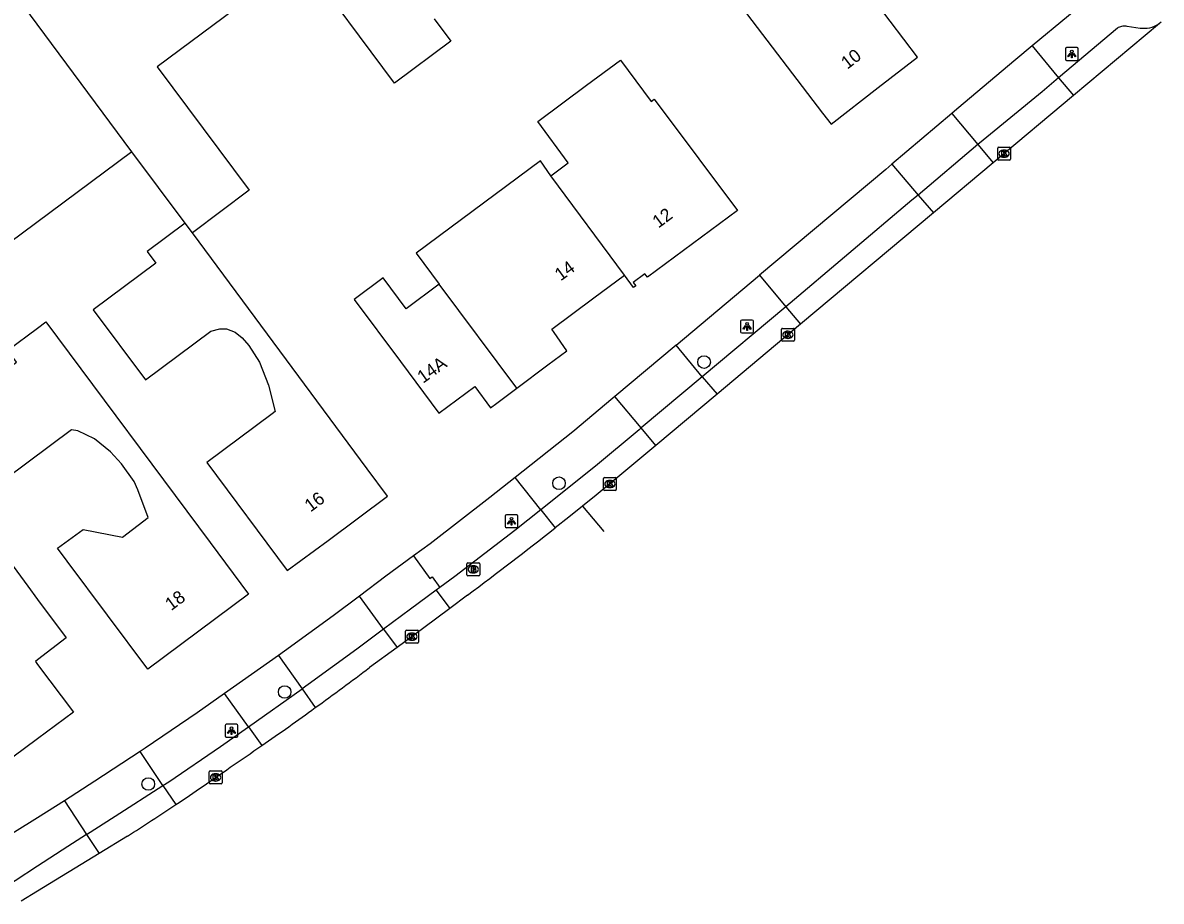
# Model space of a CAD drawing. Extents: x 156651 to 158072, y 387631 to 388990.
# Drawn here: x 157498.9 to 157587.2, y 387835.5 to 387903.7 of the extents above; entities that cross this region are included whole.
import ezdxf

# ---------------------------------------------------------------- set-up
doc = ezdxf.new("R2010")
doc.units = 0
for name, color, linetype in [('IMGEO_Boom', 7, 'Continuous'), ('IMGEO_Brandkraan', 7, 'Continuous'), ('IMGEO_Kolk', 7, 'Continuous'), ('IMGEO_Lichtpunt', 7, 'Continuous'), ('IMGEO_Pand', 7, 'Continuous'), ('IMGEO_Pand_nummerreeks', 7, 'Continuous'), ('IMGEO_Rijbaan_lokaal_open', 7, 'Continuous'), ('IMGEO_Voetpad_open', 7, 'Continuous')]:
    doc.layers.add(name, color=color, linetype=linetype)

msp = doc.modelspace()

# ---------------------------------------------------------------- linework, layer by layer
at = {"layer": 'IMGEO_Boom'}
for centre in [(157551.702, 387877.341), (157540.452, 387867.941), (157519.169, 387851.758), (157508.585, 387844.622)]:
    msp.add_circle(centre, 0.489, dxfattribs=at)
at = {"layer": 'IMGEO_Brandkraan'}
for p, q in [((157533.297, 387860.84), (157533.297, 387861.692)), ((157533.372, 387861.766), (157534.224, 387861.766)), ((157534.298, 387861.692), (157534.298, 387860.84)), ((157534.224, 387860.766), (157533.372, 387860.766)), ((157533.808, 387860.986), (157533.783, 387860.986)), ((157533.785, 387861.546), (157533.81, 387861.546))]:
    msp.add_line(p, q, dxfattribs=at)
for points in [[(157533.297, 387860.84), (157533.297, 387861.692)], [(157533.372, 387861.766), (157534.224, 387861.766)], [(157534.298, 387861.692), (157534.298, 387860.84)], [(157534.224, 387860.766), (157533.372, 387860.766)], [(157533.645, 387861.466), (157533.645, 387861.066), (157533.858, 387861.066)], [(157533.876, 387861.466), (157533.645, 387861.466)], [(157533.824, 387861.385), (157533.77, 387861.385), (157533.77, 387861.309)], [(157533.77, 387861.309), (157533.823, 387861.309)], [(157533.832, 387861.233), (157533.77, 387861.233), (157533.77, 387861.152)], [(157533.77, 387861.152), (157533.832, 387861.152)]]:
    msp.add_lwpolyline(points, dxfattribs=at)
for centre, radius, start, end in [((157533.374, 387861.69), 0.0765, 91.55205, 178.44795), ((157533.374, 387861.69), 0.0765, 91.55205, 178.44795), ((157534.222, 387861.69), 0.0765, 1.55205, 88.44795), ((157534.222, 387861.69), 0.0765, 1.55205, 88.44795), ((157533.374, 387860.842), 0.0765, 181.55205, 268.44795), ((157533.374, 387860.842), 0.0765, 181.55205, 268.44795), ((157533.825, 387861.347), 0.0379, 267.82845, 90.93552), ((157533.833, 387861.192), 0.0404, 269.87594, 90.50774), ((157533.864, 387861.317), 0.251, 268.66757, 293.53466), ((157533.88, 387861.321), 0.145, 59.4692, 91.53667), ((157533.905, 387861.368), 0.0922, 285.51372, 58.15012), ((157533.91, 387861.176), 0.105, 301.31148, 78.98903), ((157534.222, 387860.842), 0.0765, 271.55205, 358.44795), ((157534.222, 387860.842), 0.0765, 271.55205, 358.44795)]:
    msp.add_arc(centre, radius, start, end, dxfattribs=at)
for centre, major_axis, ratio, start_param, end_param in [((157533.784, 387861.266), (-0.387, 0.002), 0.722429, 4.712389, 7.853982), ((157533.809, 387861.266), (-0.39, 0.002), 0.717154, 1.570796, 4.712389)]:
    msp.add_ellipse(centre, major_axis=major_axis, ratio=ratio, start_param=start_param, end_param=end_param, dxfattribs=at)
at = {"layer": 'IMGEO_Kolk'}
for p, q in [((157574.484, 387893.08), (157574.484, 387893.932)), ((157574.559, 387894.006), (157575.411, 387894.006)), ((157574.972, 387893.786), (157574.997, 387893.786)), ((157575.485, 387893.932), (157575.485, 387893.08)), ((157575.411, 387893.006), (157574.559, 387893.006)), ((157574.995, 387893.226), (157574.97, 387893.226)), ((157557.708, 387879.03), (157557.708, 387879.882)), ((157557.783, 387879.956), (157558.635, 387879.956)), ((157558.196, 387879.736), (157558.221, 387879.736)), ((157558.709, 387879.882), (157558.709, 387879.03)), ((157558.635, 387878.956), (157557.783, 387878.956)), ((157558.219, 387879.176), (157558.194, 387879.176)), ((157543.896, 387867.463), (157543.896, 387868.315)), ((157543.971, 387868.389), (157544.823, 387868.389)), ((157544.384, 387868.169), (157544.409, 387868.169)), ((157544.897, 387868.315), (157544.897, 387867.463)), ((157544.823, 387867.389), (157543.971, 387867.389)), ((157544.407, 387867.609), (157544.382, 387867.609)), ((157528.542, 387855.624), (157528.542, 387856.476)), ((157528.617, 387856.55), (157529.469, 387856.55)), ((157529.03, 387856.33), (157529.055, 387856.33)), ((157529.543, 387856.476), (157529.543, 387855.624)), ((157529.469, 387855.55), (157528.617, 387855.55)), ((157529.053, 387855.77), (157529.028, 387855.77)), ((157513.311, 387844.706), (157513.311, 387845.558)), ((157513.386, 387845.632), (157514.238, 387845.632)), ((157513.822, 387844.852), (157513.797, 387844.852)), ((157513.799, 387845.412), (157513.824, 387845.412)), ((157514.312, 387845.558), (157514.312, 387844.706)), ((157514.238, 387844.632), (157513.386, 387844.632))]:
    msp.add_line(p, q, dxfattribs=at)
for points in [[(157574.484, 387893.08), (157574.484, 387893.932)], [(157574.559, 387894.006), (157575.411, 387894.006)], [(157574.805, 387893.706), (157574.928, 387893.706), (157574.928, 387893.555), (157575.058, 387893.706), (157575.222, 387893.706), (157575.076, 387893.555), (157575.229, 387893.306), (157575.077, 387893.306), (157574.992, 387893.47), (157574.928, 387893.403), (157574.928, 387893.306), (157574.805, 387893.306), (157574.805, 387893.706)], [(157575.485, 387893.932), (157575.485, 387893.08)], [(157575.411, 387893.006), (157574.559, 387893.006)], [(157557.708, 387879.03), (157557.708, 387879.882)], [(157557.783, 387879.956), (157558.635, 387879.956)], [(157558.029, 387879.656), (157558.152, 387879.656), (157558.152, 387879.505), (157558.282, 387879.656), (157558.446, 387879.656), (157558.3, 387879.505), (157558.453, 387879.256), (157558.301, 387879.256), (157558.216, 387879.42), (157558.152, 387879.353), (157558.152, 387879.256), (157558.029, 387879.256), (157558.029, 387879.656)], [(157558.709, 387879.882), (157558.709, 387879.03)], [(157558.635, 387878.956), (157557.783, 387878.956)], [(157543.896, 387867.463), (157543.896, 387868.315)], [(157543.971, 387868.389), (157544.823, 387868.389)], [(157544.217, 387868.089), (157544.34, 387868.089), (157544.34, 387867.938), (157544.47, 387868.089), (157544.634, 387868.089), (157544.488, 387867.938), (157544.641, 387867.689), (157544.489, 387867.689), (157544.404, 387867.853), (157544.34, 387867.786), (157544.34, 387867.689), (157544.217, 387867.689), (157544.217, 387868.089)], [(157544.897, 387868.315), (157544.897, 387867.463)], [(157544.823, 387867.389), (157543.971, 387867.389)], [(157528.542, 387855.624), (157528.542, 387856.476)], [(157528.617, 387856.55), (157529.469, 387856.55)], [(157529.543, 387856.476), (157529.543, 387855.624)], [(157529.469, 387855.55), (157528.617, 387855.55)], [(157528.863, 387856.25), (157528.986, 387856.25), (157528.986, 387856.099), (157529.116, 387856.25), (157529.28, 387856.25), (157529.134, 387856.099), (157529.287, 387855.85), (157529.135, 387855.85), (157529.05, 387856.014), (157528.986, 387855.947), (157528.986, 387855.85), (157528.863, 387855.85), (157528.863, 387856.25)], [(157513.311, 387844.706), (157513.311, 387845.558)], [(157513.386, 387845.632), (157514.238, 387845.632)], [(157513.632, 387845.332), (157513.755, 387845.332), (157513.755, 387845.181), (157513.885, 387845.332), (157514.049, 387845.332), (157513.903, 387845.181), (157514.056, 387844.932), (157513.904, 387844.932), (157513.819, 387845.096), (157513.755, 387845.029), (157513.755, 387844.932), (157513.632, 387844.932), (157513.632, 387845.332)], [(157514.312, 387845.558), (157514.312, 387844.706)], [(157514.238, 387844.632), (157513.386, 387844.632)]]:
    msp.add_lwpolyline(points, dxfattribs=at)
for centre, start, end in [((157574.561, 387893.93), 91.55205, 178.44795), ((157574.561, 387893.93), 91.55205, 178.44795), ((157575.409, 387893.93), 1.55205, 88.44795), ((157575.409, 387893.93), 1.55205, 88.44795), ((157574.561, 387893.082), 181.55205, 268.44795), ((157574.561, 387893.082), 181.55205, 268.44795), ((157575.409, 387893.082), 271.55205, 358.44795), ((157575.409, 387893.082), 271.55205, 358.44795), ((157557.785, 387879.88), 91.55205, 178.44795), ((157557.785, 387879.88), 91.55205, 178.44795), ((157558.633, 387879.88), 1.55205, 88.44795), ((157558.633, 387879.88), 1.55205, 88.44795), ((157557.785, 387879.032), 181.55205, 268.44795), ((157557.785, 387879.032), 181.55205, 268.44795), ((157558.633, 387879.032), 271.55205, 358.44795), ((157558.633, 387879.032), 271.55205, 358.44795), ((157543.973, 387868.313), 91.55205, 178.44795), ((157543.973, 387868.313), 91.55205, 178.44795), ((157544.821, 387868.313), 1.55205, 88.44795), ((157544.821, 387868.313), 1.55205, 88.44795), ((157543.973, 387867.465), 181.55205, 268.44795), ((157543.973, 387867.465), 181.55205, 268.44795), ((157544.821, 387867.465), 271.55205, 358.44795), ((157544.821, 387867.465), 271.55205, 358.44795), ((157528.619, 387856.474), 91.55205, 178.44795), ((157528.619, 387856.474), 91.55205, 178.44795), ((157529.467, 387856.474), 1.55205, 88.44795), ((157529.467, 387856.474), 1.55205, 88.44795), ((157528.619, 387855.626), 181.55205, 268.44795), ((157528.619, 387855.626), 181.55205, 268.44795), ((157529.467, 387855.626), 271.55205, 358.44795), ((157529.467, 387855.626), 271.55205, 358.44795), ((157513.388, 387845.556), 91.55205, 178.44795), ((157513.388, 387845.556), 91.55205, 178.44795), ((157514.236, 387845.556), 1.55205, 88.44795), ((157514.236, 387845.556), 1.55205, 88.44795), ((157513.388, 387844.708), 181.55205, 268.44795), ((157513.388, 387844.708), 181.55205, 268.44795), ((157514.236, 387844.708), 271.55205, 358.44795), ((157514.236, 387844.708), 271.55205, 358.44795)]:
    msp.add_arc(centre, 0.0765, start, end, dxfattribs=at)
for centre, major_axis, ratio, start_param, end_param in [((157574.971, 387893.506), (-0.387, 0.002), 0.722429, 4.712389, 7.853982), ((157574.996, 387893.506), (-0.39, 0.002), 0.717154, 1.570796, 4.712389), ((157558.195, 387879.456), (-0.387, 0.002), 0.722429, 4.712389, 7.853982), ((157558.22, 387879.456), (-0.39, 0.002), 0.717154, 1.570796, 4.712389), ((157544.383, 387867.889), (-0.387, 0.002), 0.722429, 4.712389, 7.853982), ((157544.408, 387867.889), (-0.39, 0.002), 0.717154, 1.570796, 4.712389), ((157529.029, 387856.05), (-0.387, 0.002), 0.722429, 4.712389, 7.853982), ((157529.054, 387856.05), (-0.39, 0.002), 0.717154, 1.570796, 4.712389), ((157513.798, 387845.132), (-0.387, 0.002), 0.722429, 4.712389, 7.853982), ((157513.823, 387845.132), (-0.39, 0.002), 0.717154, 1.570796, 4.712389)]:
    msp.add_ellipse(centre, major_axis=major_axis, ratio=ratio, start_param=start_param, end_param=end_param, dxfattribs=at)
at = {"layer": 'IMGEO_Lichtpunt'}
for p, q in [((157579.739, 387901.633), (157579.739, 387900.826)), ((157579.739, 387901.633), (157579.739, 387900.826)), ((157580.641, 387901.728), (157579.833, 387901.728)), ((157580.641, 387901.728), (157579.833, 387901.728)), ((157580.735, 387900.826), (157580.735, 387901.633)), ((157580.735, 387900.826), (157580.735, 387901.633)), ((157579.833, 387900.732), (157580.641, 387900.732)), ((157579.833, 387900.732), (157580.641, 387900.732)), ((157554.541, 387880.506), (157554.541, 387879.699)), ((157554.541, 387880.506), (157554.541, 387879.699)), ((157555.443, 387880.601), (157554.635, 387880.601)), ((157555.443, 387880.601), (157554.635, 387880.601)), ((157555.537, 387879.699), (157555.537, 387880.506)), ((157555.537, 387879.699), (157555.537, 387880.506)), ((157554.635, 387879.605), (157555.443, 387879.605)), ((157554.635, 387879.605), (157555.443, 387879.605)), ((157536.271, 387865.402), (157536.271, 387864.595)), ((157536.271, 387865.402), (157536.271, 387864.595)), ((157537.173, 387865.497), (157536.365, 387865.497)), ((157537.173, 387865.497), (157536.365, 387865.497)), ((157537.267, 387864.595), (157537.267, 387865.402)), ((157537.267, 387864.595), (157537.267, 387865.402)), ((157536.365, 387864.501), (157537.173, 387864.501)), ((157536.365, 387864.501), (157537.173, 387864.501)), ((157514.542, 387849.156), (157514.542, 387848.349)), ((157514.542, 387849.156), (157514.542, 387848.349)), ((157515.444, 387849.251), (157514.636, 387849.251)), ((157515.444, 387849.251), (157514.636, 387849.251)), ((157515.538, 387848.349), (157515.538, 387849.156)), ((157515.538, 387848.349), (157515.538, 387849.156)), ((157514.636, 387848.255), (157515.444, 387848.255)), ((157514.636, 387848.255), (157515.444, 387848.255))]:
    msp.add_line(p, q, dxfattribs=at)
for points in [[(157580.113, 387901.297), (157580.152, 387901.269), (157579.964, 387901.007), (157579.926, 387901.034), (157580.113, 387901.297)], [(157580.215, 387901.249), (157580.262, 387901.249), (157580.262, 387900.927), (157580.215, 387900.927), (157580.215, 387901.249)], [(157580.325, 387901.269), (157580.363, 387901.296), (157580.55, 387901.034), (157580.511, 387901.006), (157580.325, 387901.269)], [(157554.915, 387880.17), (157554.954, 387880.142), (157554.766, 387879.88), (157554.728, 387879.907), (157554.915, 387880.17)], [(157555.017, 387880.122), (157555.064, 387880.122), (157555.064, 387879.8), (157555.017, 387879.8), (157555.017, 387880.122)], [(157555.127, 387880.142), (157555.165, 387880.169), (157555.352, 387879.907), (157555.313, 387879.879), (157555.127, 387880.142)], [(157536.645, 387865.066), (157536.684, 387865.038), (157536.496, 387864.776), (157536.458, 387864.803), (157536.645, 387865.066)], [(157536.747, 387865.018), (157536.794, 387865.018), (157536.794, 387864.696), (157536.747, 387864.696), (157536.747, 387865.018)], [(157536.857, 387865.038), (157536.895, 387865.065), (157537.082, 387864.803), (157537.043, 387864.775), (157536.857, 387865.038)], [(157514.916, 387848.82), (157514.955, 387848.792), (157514.767, 387848.53), (157514.729, 387848.557), (157514.916, 387848.82)], [(157515.018, 387848.772), (157515.065, 387848.772), (157515.065, 387848.45), (157515.018, 387848.45), (157515.018, 387848.772)], [(157515.128, 387848.792), (157515.166, 387848.819), (157515.353, 387848.557), (157515.314, 387848.529), (157515.128, 387848.792)]]:
    msp.add_lwpolyline(points, dxfattribs=at)
for centre in [(157580.238, 387901.431), (157555.04, 387880.304), (157536.77, 387865.2), (157515.041, 387848.954)]:
    msp.add_circle(centre, 0.0994, dxfattribs=at)
for centre, start, end in [((157579.833, 387901.633), 90, 180), ((157579.833, 387901.633), 90, 180), ((157580.641, 387901.633), 0, 90), ((157580.641, 387901.633), 0, 90), ((157579.833, 387900.826), 180, 270), ((157579.833, 387900.826), 180, 270), ((157580.641, 387900.826), 270, 0), ((157580.641, 387900.826), 270, 360), ((157554.635, 387880.506), 90, 180), ((157554.635, 387880.506), 90, 180), ((157555.443, 387880.506), 0, 90), ((157555.443, 387880.506), 0, 90), ((157554.635, 387879.699), 180, 270), ((157554.635, 387879.699), 180, 270), ((157555.443, 387879.699), 270, 0), ((157555.443, 387879.699), 270, 360), ((157536.365, 387865.402), 90, 180), ((157536.365, 387865.402), 90, 180), ((157537.173, 387865.402), 0, 90), ((157537.173, 387865.402), 0, 90), ((157536.365, 387864.595), 180, 270), ((157536.365, 387864.595), 180, 270), ((157537.173, 387864.595), 270, 0), ((157537.173, 387864.595), 270, 360), ((157514.636, 387849.156), 90, 180), ((157514.636, 387849.156), 90, 180), ((157515.444, 387849.156), 0, 90), ((157515.444, 387849.156), 0, 90), ((157514.636, 387848.349), 180, 270), ((157514.636, 387848.349), 180, 270), ((157515.444, 387848.349), 270, 0), ((157515.444, 387848.349), 270, 360)]:
    msp.add_arc(centre, 0.0946, start, end, dxfattribs=at)
at = {"layer": 'IMGEO_Pand'}
for points in [[(157564.546, 387905.917), (157565.739, 387906.84), (157559.559, 387914.828), (157551.643, 387908.71), (157554.238, 387905.353), (157560.893, 387896.651), (157561.555, 387895.799), (157565.21, 387898.625), (157568.268, 387900.982), (157566.134, 387903.771), (157564.546, 387905.917)], [(157530.769, 387903.97), (157532.065, 387902.226), (157527.692, 387898.974), (157520.532, 387908.604), (157509.286, 387900.242), (157516.425, 387890.66), (157512.006, 387887.368)], [(157507.314, 387893.658), (157498.856, 387905.046)], [(157539.812, 387891.788), (157541.168, 387892.799), (157538.797, 387895.99), (157542.59, 387898.807), (157545.214, 387900.756), (157547.601, 387897.554), (157547.84, 387897.732), (157551.297, 387893.095), (157554.286, 387889.086), (157547.311, 387883.916), (157547.121, 387884.174), (157546.213, 387883.502), (157546.404, 387883.243), (157546.234, 387883.118), (157545.523, 387884.078)], [(157507.314, 387893.658), (157496.696, 387885.763)], [(157511.446, 387888.12), (157507.314, 387893.658)], [(157539.812, 387891.788), (157539.005, 387892.943), (157529.369, 387885.783), (157531.161, 387883.382)], [(157545.523, 387884.078), (157539.812, 387891.788)], [(157511.446, 387888.12), (157508.498, 387885.926), (157509.184, 387885.004), (157504.321, 387881.385), (157508.361, 387875.957), (157513.436, 387879.738), (157514.151, 387879.918), (157514.654, 387879.922), (157515.331, 387879.664), (157515.877, 387879.23), (157516.399, 387878.638), (157517.209, 387877.329), (157517.919, 387875.546), (157518.427, 387873.505), (157518.204, 387873.34), (157513.121, 387869.551), (157519.359, 387861.18), (157522.544, 387863.503), (157527.152, 387866.931), (157525.577, 387869.057), (157512.006, 387887.368)], [(157512.006, 387887.368), (157511.446, 387888.12)], [(157531.161, 387883.382), (157528.602, 387881.475), (157526.821, 387883.865), (157524.567, 387882.185), (157528.149, 387877.38), (157531.137, 387873.371), (157533.912, 387875.44), (157535.134, 387873.801), (157535.627, 387874.168), (157537.176, 387875.323)], [(157537.176, 387875.323), (157539.593, 387877.124), (157541.07, 387878.225), (157540.064, 387879.64), (157539.886, 387879.89), (157543.161, 387882.323), (157545.523, 387884.078)], [(157537.176, 387875.323), (157531.161, 387883.382)], [(157500, 387879.968), (157500.652, 387880.45), (157513.377, 387863.362), (157516.363, 387859.351), (157508.544, 387853.529), (157502.306, 387861.9), (157501.543, 387862.923), (157503.535, 387864.366), (157506.6, 387863.755), (157508.574, 387865.291), (157507.771, 387867.433), (157507.48, 387868.084), (157506.508, 387869.44), (157505.667, 387870.369), (157504.416, 387871.377), (157503.122, 387872.018), (157502.621, 387872.087), (157497.537, 387868.299), (157493.492, 387873.727), (157498.37, 387877.333), (157497.687, 387878.258), (157500, 387879.968)], [(157493.742, 387856.55), (157491.161, 387860.02), (157496.365, 387863.844), (157499.242, 387859.964), (157500, 387858.942), (157502.221, 387855.947), (157500, 387854.248), (157499.828, 387854.116), (157500, 387853.888), (157502.786, 387850.203), (157500, 387848.131), (157497.173, 387846.028), (157494.204, 387850.052), (157490.937, 387854.48), (157493.742, 387856.55)]]:
    msp.add_lwpolyline(points, dxfattribs=at)
at = {"layer": 'IMGEO_Rijbaan_lokaal_open'}
for points in [[(157587.035, 387903.596), (157580.354, 387898.001)], [(157587.171, 387903.71), (157587.035, 387903.596)], [(157580.354, 387898.001), (157574.13, 387892.788)], [(157574.13, 387892.788), (157569.499, 387888.91)], [(157569.499, 387888.91), (157559.184, 387880.271)], [(157559.184, 387880.271), (157552.71, 387874.849)], [(157552.71, 387874.849), (157547.965, 387870.875)], [(157547.965, 387870.875), (157544.398, 387867.888), (157543.341, 387867.029), (157542.281, 387866.174)], [(157542.281, 387866.174), (157541.217, 387865.324), (157540.149, 387864.479)], [(157542.281, 387866.174), (157543.925, 387864.194)], [(157533.363, 387859.279), (157531.982, 387858.239)], [(157531.982, 387858.239), (157529.967, 387856.723), (157527.887, 387855.207)], [(157527.887, 387855.207), (157525.751, 387853.65)], [(157506.967, 387840.575), (157504.771, 387839.232)], [(157504.771, 387839.232), (157500, 387836.314), (157498.723, 387835.533)]]:
    msp.add_lwpolyline(points, dxfattribs=at)
for centre, radius, start, end in [((157342.11, 388115.892), 320.044, 306.69706, 308.22764), ((157362.675, 388070.149), 271.045, 305.88333, 306.98847), ((157355.093, 388081.035), 284.309, 304.81221, 305.83554), ((157368.93, 388061.315), 260.22, 304.1308, 304.7896), ((157398.93, 388010.357), 201.241, 303.74545, 305.20119), ((157397.844, 388012.04), 203.243, 302.4733, 303.73634)]:
    msp.add_arc(centre, radius, start, end, dxfattribs=at)
at = {"layer": 'IMGEO_Voetpad_open'}
for points in [[(157585.134, 387906.15), (157584.032, 387907.609), (157579.986, 387904.199), (157577.159, 387901.855)], [(157587.035, 387903.596), (157586.938, 387903.529), (157586.779, 387903.435), (157586.612, 387903.356), (157586.439, 387903.292), (157586.261, 387903.244), (157586.079, 387903.212), (157585.895, 387903.197), (157585.71, 387903.198), (157585.526, 387903.215), (157584.536, 387903.369), (157584.448, 387903.385), (157584.359, 387903.394), (157584.269, 387903.394), (157584.18, 387903.386), (157584.092, 387903.37), (157584.006, 387903.347), (157583.922, 387903.316), (157583.841, 387903.277), (157583.781, 387903.243), (157579.207, 387899.385)], [(157577.159, 387901.855), (157575.881, 387900.795), (157571.324, 387896.952), (157570.926, 387896.615)], [(157577.159, 387901.855), (157579.207, 387899.385)], [(157579.207, 387899.385), (157577.924, 387898.302), (157573.358, 387894.549), (157572.947, 387894.202)], [(157579.207, 387899.385), (157580.354, 387898.001)], [(157570.926, 387896.615), (157566.283, 387892.678)], [(157570.926, 387896.615), (157572.947, 387894.202)], [(157572.947, 387894.202), (157568.317, 387890.296)], [(157572.947, 387894.202), (157574.13, 387892.788)], [(157566.283, 387892.678), (157565.798, 387892.267), (157556.012, 387884.082)], [(157566.283, 387892.678), (157568.317, 387890.296)], [(157568.317, 387890.296), (157567.831, 387889.886), (157558.041, 387881.636)], [(157568.317, 387890.296), (157569.499, 387888.91)], [(157549.538, 387878.658), (157556.012, 387884.082)], [(157556.012, 387884.082), (157558.041, 387881.636)], [(157558.041, 387881.636), (157551.57, 387876.208)], [(157558.041, 387881.636), (157559.184, 387880.271)], [(157549.538, 387878.658), (157544.783, 387874.674)], [(157551.57, 387876.208), (157549.538, 387878.658)], [(157551.57, 387876.208), (157546.829, 387872.231)], [(157551.57, 387876.208), (157552.71, 387874.849)], [(157544.783, 387874.674), (157544.63, 387874.546), (157541.523, 387871.943), (157537.046, 387868.396)], [(157546.829, 387872.231), (157544.783, 387874.674)], [(157546.829, 387872.231), (157546.665, 387872.093), (157543.289, 387869.262), (157539.036, 387865.884)], [(157547.965, 387870.875), (157546.829, 387872.231)], [(157537.046, 387868.396), (157535.077, 387866.836), (157530.45, 387863.258), (157529.155, 387862.308)], [(157539.036, 387865.884), (157537.046, 387868.396)], [(157539.036, 387865.884), (157537.016, 387864.28), (157532.369, 387860.712), (157531.217, 387859.862)], [(157539.036, 387865.884), (157540.149, 387864.479)], [(157529.155, 387862.308), (157527.024, 387860.744), (157524.976, 387859.201)], [(157529.155, 387862.308), (157530.436, 387860.571), (157530.603, 387860.695), (157531.217, 387859.862)], [(157531.217, 387859.862), (157530.923, 387859.645)], [(157524.976, 387859.201), (157522.927, 387857.658), (157519.15, 387854.92), (157518.688, 387854.594)], [(157526.848, 387856.632), (157524.976, 387859.201)], [(157530.923, 387859.645), (157528.935, 387858.179), (157526.848, 387856.632)], [(157530.923, 387859.645), (157531.982, 387858.239)], [(157526.848, 387856.632), (157524.771, 387855.091), (157520.994, 387852.338), (157520.517, 387852.001)], [(157526.848, 387856.632), (157527.887, 387855.207)], [(157518.688, 387854.594), (157514.513, 387851.648)], [(157518.688, 387854.594), (157520.517, 387852.001)], [(157516.36, 387849.065), (157520.517, 387852.001)], [(157520.517, 387852.001), (157521.545, 387850.545)], [(157514.513, 387851.648), (157512.391, 387850.15), (157508.357, 387847.413), (157507.954, 387847.148)], [(157516.36, 387849.065), (157514.513, 387851.648)], [(157509.728, 387844.502), (157510.179, 387844.792), (157514.186, 387847.529), (157516.36, 387849.065)], [(157516.36, 387849.065), (157517.402, 387847.609)], [(157507.954, 387847.148), (157504.436, 387844.833), (157502.087, 387843.329)], [(157509.728, 387844.502), (157507.954, 387847.148)], [(157503.804, 387840.708), (157506.018, 387842.12), (157509.728, 387844.502)], [(157509.728, 387844.502), (157510.72, 387843.022)], [(157502.087, 387843.329), (157500.69, 387842.434), (157500, 387842.004), (157496.617, 387839.898), (157496.206, 387839.647)], [(157502.087, 387843.329), (157503.804, 387840.708)], [(157503.804, 387840.708), (157502.337, 387839.773), (157500, 387838.248), (157498.268, 387837.117), (157497.892, 387836.892)], [(157503.804, 387840.708), (157504.771, 387839.232)]]:
    msp.add_lwpolyline(points, dxfattribs=at)

# ---------------------------------------------------------------- texts
at = {"layer": 'IMGEO_Pand_nummerreeks'}
for s, rotation, p in [('10', 37.66625, (157562.819, 387900.006)), ('12', 36.54519, (157548.166, 387887.687)), ('14', 35.99894, (157540.578, 387883.59)), ('14A', 35.41452, (157529.904, 387875.654)), ('16', 36.64638, (157521.176, 387865.672)), ('18', 36.67124, (157510.362, 387858.024))]:
    msp.add_text(s, height=1, rotation=rotation, dxfattribs=at).set_placement(p)

doc.saveas('drawing.dxf')
